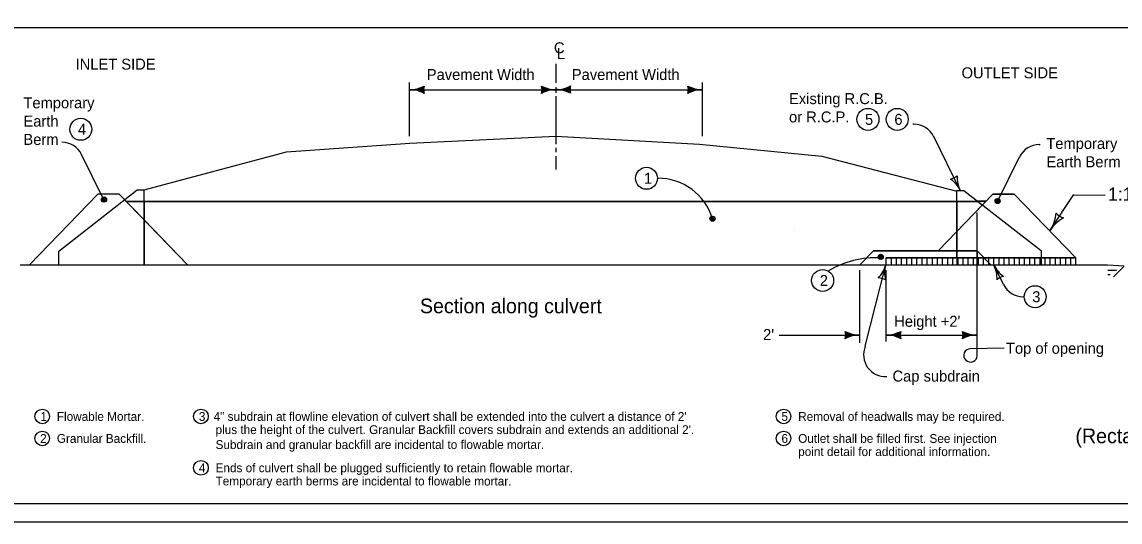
# Model space of a CAD drawing. Extents: x 4574 to 81668, y 5908 to 13780.
# Drawn here: x 10645 to 12144, y 7924 to 8607 of the extents above; entities that cross this region are included whole.
import ezdxf

# ---------------------------------------------------------------- set-up
doc = ezdxf.new("R2010")
doc.units = 0
for name, color, linetype in [('dsnCellElements', 7, 'Continuous'), ('DsnShtRevisedText', 7, 'Continuous'), ('Level 1', 7, 'Continuous'), ('Level 8', 7, 'Continuous'), ('SheetBorder', 7, 'Continuous'), ('ShtPlotIdentification', 7, 'Continuous')]:
    doc.layers.add(name, color=color, linetype=linetype)

msp = doc.modelspace()

# ---------------------------------------------------------------- linework, layer by layer
at = {"layer": 'dsnCellElements'}
for p, q in [((11373.8, 8523.5), (11373.8, 8549.6)), ((11173.8, 8450.5), (11173.8, 8524.1)), ((11373.8, 8509.9), (11373.8, 8517.4)), ((11573.8, 8450.5), (11573.8, 8524.1)), ((11173.8, 8514.1), (11193, 8514.1)), ((11173.8, 8514.1), (11373.8, 8514.1)), ((11373.9, 8514.1), (11354.7, 8514.1)), ((11373.7, 8514.2), (11392.9, 8514.2)), ((11373.8, 8514.1), (11573.8, 8514.1)), ((11373.8, 8439.9), (11373.8, 8505.4)), ((11573.8, 8514.1), (11554.6, 8514.1)), ((11862.4, 8467), (11861.1, 8467)), ((11005.8, 8429.1), (11174.4, 8440.9)), ((11174.4, 8440.9), (11373.7, 8450.6)), ((11373.7, 8450.6), (11569.9, 8439.8)), ((11925.6, 8376.4), (11889.4, 8450.3)), ((10756.6, 8363.6), (10726.1, 8425.8)), ((10811.4, 8377.2), (11005.8, 8429.1)), ((11373.8, 8429), (11373.8, 8434.7)), ((11569.9, 8439.8), (11736.7, 8423.2)), ((12033.6, 8439.3), (12034.9, 8439.3)), ((11373.8, 8405.3), (11373.8, 8423.2)), ((11736.7, 8423.2), (11920.8, 8375.7)), ((11976.1, 8360.4), (12006.6, 8422.6)), ((10654.8, 8275.1), (10748.1, 8371.7)), ((10694.9, 8293.9), (10801.9, 8377.2)), ((10777.2, 8371.7), (10748.1, 8371.7)), ((10870.7, 8274.9), (10777.2, 8371.7)), ((10801.9, 8377.2), (10811.4, 8377.2)), ((10811.4, 8361.7), (10811.4, 8377.2)), ((11895.6, 8294.3), (11970.3, 8371.7)), ((11920.8, 8376.4), (11930.5, 8376.4)), ((11920.8, 8361.7), (11920.8, 8376.4)), ((11930.5, 8376.3), (12036.5, 8294.1)), ((11970.3, 8371.7), (11999.4, 8371.7)), ((12083.6, 8284.5), (11999.4, 8371.7)), ((12048.4, 8322.2), (12080.6, 8371.2)), ((12080, 8370.3), (12123.6, 8370.4)), ((10786.9, 8361.7), (11949.3, 8361.7)), ((10811.4, 8361.7), (10811.3, 8275.1)), ((11920.8, 8361.7), (11920.8, 8275.1)), ((11949.2, 8361.8), (11960.7, 8361.8)), ((11948.7, 8151.4), (11948.7, 8346.4)), ((10695, 8274.9), (10695, 8293.9)), ((11788.7, 8275.1), (11807.3, 8294.3)), ((11807.3, 8294.3), (11948.7, 8294.3)), ((11967.3, 8275.1), (11948.7, 8294.3)), ((12036.4, 8275.1), (12036.4, 8294)), ((10642.2, 8275.1), (12126.8, 8275.1)), ((11788.7, 8168.6), (11788.7, 8267.9)), ((11796, 8163.9), (11823.9, 8275.1)), ((11824.5, 8170.2), (11824.5, 8267.9)), ((11984.7, 8248.3), (11971.6, 8274.9)), ((12126.8, 8275.1), (12149.3, 8273.7)), ((12139.2, 8267.4), (12127.2, 8267.4)), ((12130.5, 8261.6), (12127.2, 8261.6)), ((12130.5, 8261.6), (12130.5, 8261.6)), ((12148.8, 8272.9), (12134.7, 8258.8)), ((12136.3, 8267.4), (12136.3, 8267.4)), ((11678.6, 8179.2), (11788.5, 8179.2)), ((11788.5, 8179.2), (11769.3, 8179.2)), ((11824.5, 8179.2), (11843.7, 8179.2)), ((11824.5, 8179.2), (11948.7, 8179.2)), ((11948.7, 8179.2), (11929.5, 8179.2)), ((11985.8, 8161.1), (11939.6, 8160.5)), ((11801.2, 8132.6), (11802.1, 8131.6))]:
    msp.add_line(p, q, dxfattribs=at)
for points in [[(11192.6, 8510.6), (11191.9, 8514.1), (11192.6, 8517.7), (11188.3, 8515.7), (11181.5, 8514.1), (11188.8, 8512.4), (11192, 8511), (11191.2, 8514.1), (11191.5, 8516.4), (11188.7, 8515.1), (11184.9, 8514.1), (11188.9, 8513), (11191, 8512.2), (11190.6, 8515.3), (11187.9, 8514.1), (11190, 8513.4), (11190.1, 8514.5), (11189.1, 8514.2)], [(11355.1, 8517.7), (11355.8, 8514.1), (11355.1, 8510.5), (11359.4, 8512.6), (11366.2, 8514.1), (11358.9, 8515.8), (11355.7, 8517.3), (11356.5, 8514.1), (11356.2, 8511.8), (11359, 8513.2), (11362.8, 8514.1), (11358.8, 8515.3), (11356.7, 8516), (11357.1, 8513), (11359.9, 8514.1), (11357.7, 8514.8), (11357.6, 8513.8), (11358.7, 8514.1)], [(11392.5, 8510.6), (11391.8, 8514.2), (11392.6, 8517.8), (11388.3, 8515.7), (11381.5, 8514.2), (11388.8, 8512.5), (11391.9, 8511.1), (11391.2, 8514.2), (11391.5, 8516.5), (11388.6, 8515.2), (11384.9, 8514.2), (11388.9, 8513), (11391, 8512.3), (11390.6, 8515.4), (11387.8, 8514.2), (11390, 8513.5), (11390, 8514.6), (11389, 8514.2)], [(11554.9, 8517.7), (11555.7, 8514.1), (11554.9, 8510.5), (11559.2, 8512.6), (11566, 8514.1), (11558.7, 8515.8), (11555.5, 8517.2), (11556.3, 8514.1), (11556, 8511.8), (11558.9, 8513.1), (11562.6, 8514.1), (11558.6, 8515.3), (11556.5, 8516), (11556.9, 8512.9), (11559.7, 8514.1), (11557.5, 8514.8), (11557.5, 8513.7), (11558.5, 8514.1)], [(10757, 8367.3), (10755.8, 8366.8), (10754, 8366.2), (10753.6, 8364.4), (10753.9, 8362.7), (10755.1, 8361.2), (10756.8, 8361.4), (10758.7, 8361.6), (10759.5, 8363.1), (10759.7, 8364.7), (10758.6, 8366.7), (10757.3, 8366.8), (10755.4, 8366.4), (10753.9, 8365.2), (10754, 8363.5), (10755.1, 8362.1), (10756.8, 8361.9), (10758.6, 8362.3), (10758.9, 8363.3), (10759.3, 8364.5), (10758.4, 8366.1), (10757.1, 8366), (10755.6, 8365.8), (10754.4, 8364.9), (10755, 8363.4), (10756.2, 8362.5), (10757.7, 8362.4), (10758.1, 8363.3), (10758.6, 8364.2), (10757.8, 8365.4), (10756.7, 8365.7), (10755.7, 8365.2), (10755.6, 8364), (10756.1, 8363.2), (10757.2, 8362.9), (10757.7, 8363.4), (10758, 8364), (10757.4, 8364.9), (10756.7, 8365.1), (10756, 8364.6), (10756.1, 8364), (10756.6, 8363.6), (10757.4, 8363.7), (10757.3, 8364.2), (10756.7, 8364.5)], [(11977, 8365.3), (11975.8, 8364.8), (11974, 8364.2), (11973.6, 8362.3), (11973.8, 8360.7), (11975, 8359.2), (11976.8, 8359.3), (11978.6, 8359.6), (11979.5, 8361.1), (11979.7, 8362.6), (11978.6, 8364.6), (11977.2, 8364.8), (11975.4, 8364.3), (11973.9, 8363.2), (11973.9, 8361.4), (11975.1, 8360), (11976.8, 8359.8), (11978.6, 8360.2), (11978.9, 8361.2), (11979.3, 8362.5), (11978.4, 8364), (11977, 8364), (11975.5, 8363.7), (11974.4, 8362.9), (11975, 8361.3), (11976.1, 8360.4), (11977.7, 8360.4), (11978.1, 8361.2), (11978.5, 8362.2), (11977.8, 8363.4), (11976.6, 8363.6), (11975.6, 8363.1), (11975.6, 8362), (11976.1, 8361.2), (11977.1, 8360.9), (11977.6, 8361.3), (11977.9, 8361.9), (11977.4, 8362.8), (11976.7, 8363), (11976, 8362.6), (11976.1, 8362), (11976.6, 8361.6), (11977.3, 8361.6), (11977.3, 8362.1), (11976.7, 8362.4)], [(11587.7, 8341.2), (11586.5, 8340.7), (11584.6, 8340.1), (11584.3, 8338.2), (11584.5, 8336.6), (11585.7, 8335.1), (11587.5, 8335.2), (11589.3, 8335.5), (11590.2, 8337), (11590.4, 8338.5), (11589.3, 8340.5), (11587.9, 8340.7), (11586.1, 8340.2), (11584.6, 8339.1), (11584.6, 8337.3), (11585.8, 8335.9), (11587.4, 8335.7), (11589.3, 8336.1), (11589.6, 8337.1), (11589.9, 8338.4), (11589.1, 8339.9), (11587.7, 8339.9), (11586.2, 8339.6), (11585.1, 8338.8), (11585.7, 8337.2), (11586.8, 8336.3), (11588.4, 8336.3), (11588.7, 8337.1), (11589.2, 8338.1), (11588.5, 8339.3), (11587.3, 8339.5), (11586.3, 8339), (11586.3, 8337.9), (11586.8, 8337.1), (11587.8, 8336.8), (11588.3, 8337.2), (11588.6, 8337.8), (11588.1, 8338.7), (11587.4, 8338.9), (11586.6, 8338.5), (11586.8, 8337.9), (11587.3, 8337.5), (11588, 8337.5), (11588, 8338), (11587.4, 8338.3)], [(11817.4, 8289.1), (11816.2, 8288.5), (11814.3, 8288), (11814, 8286.1), (11814.2, 8284.5), (11815.4, 8283), (11817.2, 8283.1), (11819, 8283.4), (11819.9, 8284.8), (11820.1, 8286.4), (11819, 8288.4), (11817.6, 8288.6), (11815.8, 8288.1), (11814.3, 8286.9), (11814.3, 8285.2), (11815.5, 8283.8), (11817.2, 8283.6), (11819, 8284), (11819.3, 8285), (11819.6, 8286.3), (11818.8, 8287.8), (11817.4, 8287.8), (11815.9, 8287.5), (11814.8, 8286.7), (11815.4, 8285.1), (11816.5, 8284.2), (11818.1, 8284.2), (11818.4, 8285), (11818.9, 8285.9), (11818.2, 8287.2), (11817, 8287.4), (11816, 8286.9), (11816, 8285.8), (11816.5, 8285), (11817.5, 8284.7), (11818, 8285.1), (11818.3, 8285.7), (11817.8, 8286.6), (11817.1, 8286.8), (11816.4, 8286.4), (11816.5, 8285.8), (11817, 8285.4), (11817.7, 8285.4), (11817.7, 8285.9), (11817.1, 8286.2)], [(11769.7, 8182.7), (11770.4, 8179.2), (11769.6, 8175.6), (11773.9, 8177.6), (11780.8, 8179.2), (11773.4, 8180.9), (11770.3, 8182.3), (11771.1, 8179.2), (11770.8, 8176.8), (11773.6, 8178.2), (11777.4, 8179.2), (11773.3, 8180.3), (11771.2, 8181.1), (11771.6, 8178), (11774.4, 8179.2), (11772.2, 8179.9), (11772.2, 8178.8), (11773.2, 8179.1)], [(11843.3, 8175.7), (11842.6, 8179.3), (11843.3, 8182.9), (11839, 8180.8), (11832.2, 8179.3), (11839.6, 8177.5), (11842.7, 8176.1), (11841.9, 8179.3), (11842.2, 8181.6), (11839.4, 8180.2), (11835.6, 8179.3), (11839.7, 8178.1), (11841.8, 8177.4), (11841.4, 8180.4), (11838.6, 8179.3), (11840.8, 8178.6), (11840.8, 8179.6), (11839.8, 8179.3)], [(11929.9, 8182.7), (11930.6, 8179.2), (11929.9, 8175.6), (11934.2, 8177.6), (11941, 8179.2), (11933.6, 8180.9), (11930.5, 8182.3), (11931.3, 8179.2), (11931, 8176.8), (11933.8, 8178.2), (11937.6, 8179.2), (11933.6, 8180.3), (11931.5, 8181.1), (11931.8, 8178), (11934.6, 8179.2), (11932.4, 8179.9), (11932.4, 8178.8), (11933.4, 8179.1)]]:
    msp.add_lwpolyline(points, dxfattribs=at)
for centre, radius in [((11799.6, 8473.6), 15), ((11839.6, 8473.6), 15), ((10725, 8460.1), 15), ((11497.3, 8393.2), 15), ((10756.7, 8364.1), 3.5), ((11976.7, 8362.1), 3.5), ((11587.4, 8338), 3.5), ((11817.1, 8285.9), 3.5), ((11737.8, 8253.7), 15), ((12027.9, 8231.5), 15), ((10672.3, 8068.1), 10), ((10889, 8068.1), 10), ((11684.4, 8068.1), 10), ((10672.3, 8038.1), 10), ((11684.4, 8038.1), 10), ((10889, 7998), 10)]:
    msp.add_circle(centre, radius, dxfattribs=at)
for centre, radius, start, end in [((11173.8, 8556.6), 42.5, 270, 298.0725), ((11209.4, 8514.1), 16.4, 162.2666, 197.7334), ((11338.3, 8514.1), 16.4, 342.2666, 17.7334), ((11373.9, 8556.6), 42.5, 241.9275, 270), ((11373.7, 8556.7), 42.5, 270, 298.0725), ((11409.4, 8514.2), 16.4, 162.2666, 197.7334), ((11538.1, 8514.1), 16.4, 342.2666, 17.7334), ((11573.8, 8556.6), 42.5, 241.9275, 270), ((11173.8, 8471.6), 42.5, 61.9275, 90), ((11373.9, 8471.6), 42.5, 90, 118.0725), ((11373.7, 8471.7), 42.5, 61.9275, 90), ((11573.8, 8471.6), 42.5, 90, 118.0725), ((11862.4, 8437), 30, 26.1599, 90), ((10699.2, 8412.5), 30, 26.1603, 90), ((12033.6, 8409.3), 30, 90, 153.8397), ((11909.9, 8408.4), 16.4, 278.427, 313.8937), ((11963.8, 8395.2), 42.5, 178.0879, 206.1604), ((11513.3, 8316), 77.2, 16.5237, 90.8016), ((11887.5, 8357.7), 42.5, 26.1604, 54.2328), ((12005.6, 8350.4), 51.2, 326.6555, 354.7279), ((12091.2, 8294.1), 51.2, 118.583, 146.6555), ((12072, 8358.1), 19.8, 218.9221, 254.3888), ((11811.2, 8156), 128.8, 87.6655, 120.5189), ((11782.8, 8286.1), 42.5, 316.8529, 344.9253), ((11864.9, 8264), 42.5, 164.9253, 192.9978), ((11933.4, 8256.2), 42.5, 358.0872, 26.1597), ((12009.7, 8293.7), 42.5, 206.1597, 234.2322), ((11814.6, 8240.7), 16.4, 57.192, 92.6587), ((11987.3, 8243), 16.4, 98.4264, 133.8931), ((12011.6, 8261.5), 30, 206.1604, 270), ((11752.9, 8179.2), 16.4, 342.2666, 17.7334), ((11788.5, 8221.7), 42.5, 241.9275, 270), ((11788.5, 8136.7), 42.5, 90, 118.0725), ((11824.5, 8221.7), 42.5, 270, 298.0725), ((11824.5, 8136.7), 42.5, 61.9275, 90), ((11860.1, 8179.2), 16.4, 162.2666, 197.7334), ((11913.1, 8179.2), 16.4, 342.2666, 17.7334), ((11948.7, 8221.7), 42.5, 241.9275, 270), ((11948.7, 8136.7), 42.5, 90, 118.0725), ((11823.7, 8152.4), 30, 157.6234, 272.9348)]:
    msp.add_arc(centre, radius, start, end, dxfattribs=at)
at = {"layer": 'Level 1'}
for points in [[(10147.5, 8599), (13252.5, 8599), (13252.5, 7949), (10147.5, 7949), (10147.5, 8599)], [(10811.4, 8361.7), (10786.9, 8361.7), (10811.4, 8336.4), (10811.4, 8361.7)]]:
    msp.add_lwpolyline(points, dxfattribs=at)
for points in [[(10777.2, 8371.7), (10748.1, 8371.7), (10654.8, 8275.1), (10811.3, 8275.1), (10811.4, 8336.4)], [(10777.2, 8371.7), (10748.1, 8371.7), (10654.8, 8275.1), (10811.3, 8275.1), (10811.4, 8336.4)], [(12083.6, 8284.5), (12083.6, 8284.5), (11999.4, 8371.7), (11970.3, 8371.7), (11920.8, 8320.4), (11920.8, 8294.3), (11948.7, 8294.3), (11958.2, 8284.5)], [(11920.8, 8320.4), (11920.8, 8361.7), (10811.4, 8361.7), (10811.4, 8336.4), (10870.5, 8275.1), (11788.7, 8275.1), (11807.3, 8294.3), (11895.6, 8294.3)], [(11955.8, 8356.7), (11949.3, 8361.7), (11920.8, 8361.7), (11920.8, 8320.4)], [(11960.7, 8361.8), (11949.2, 8361.8), (11955.8, 8356.7)], [(10811.3, 8275.1), (10870.5, 8275.1), (10811.4, 8336.4)], [(11920.8, 8294.3), (11920.8, 8320.4), (11895.6, 8294.3)], [(11920.8, 8294.3), (11807.3, 8294.3), (11788.7, 8275.1), (11824.6, 8275.1), (11824.6, 8284.5), (11920.8, 8284.5)], [(11948.7, 8284.5), (11948.7, 8294.3), (11920.8, 8294.3), (11920.8, 8284.5)], [(11958.2, 8284.5), (11948.7, 8294.3), (11948.7, 8284.5)]]:
    msp.add_lwpolyline(points, close=True, dxfattribs=at)
for centre in [(10756.7, 8364.1), (10756.7, 8364.1), (11976.7, 8362.1), (11587.4, 8338)]:
    msp.add_circle(centre, 3.5, dxfattribs=at)
at = {"layer": 'Level 8'}
for p, q in [((11824.6, 8274.9), (11824.6, 8284.5)), ((12083.6, 8284.5), (11824.6, 8284.5)), ((11831.6, 8274.9), (11831.6, 8284.5)), ((11838.6, 8274.9), (11838.6, 8284.5)), ((11845.6, 8274.9), (11845.6, 8284.5)), ((11852.6, 8274.9), (11852.6, 8284.5)), ((11859.6, 8274.9), (11859.6, 8284.5)), ((11866.6, 8274.9), (11866.6, 8284.5)), ((11873.6, 8274.9), (11873.6, 8284.5)), ((11880.6, 8274.9), (11880.6, 8284.5)), ((11887.6, 8274.9), (11887.6, 8284.5)), ((11894.6, 8274.9), (11894.6, 8284.5)), ((11901.6, 8274.9), (11901.6, 8284.5)), ((11908.6, 8274.9), (11908.6, 8284.5)), ((11915.6, 8274.9), (11915.6, 8284.5)), ((11922.6, 8274.9), (11922.6, 8284.5)), ((11929.6, 8274.9), (11929.6, 8284.5)), ((11936.6, 8274.9), (11936.6, 8284.5)), ((11943.6, 8274.9), (11943.6, 8284.5)), ((11950.6, 8274.9), (11950.6, 8284.5)), ((11957.6, 8274.9), (11957.6, 8284.5)), ((11964.6, 8274.9), (11964.6, 8284.5)), ((11971.6, 8274.9), (11971.6, 8284.5)), ((11978.6, 8274.9), (11978.6, 8284.5)), ((11985.6, 8274.9), (11985.6, 8284.5)), ((11992.6, 8274.9), (11992.6, 8284.5)), ((11999.6, 8274.9), (11999.6, 8284.5)), ((12006.6, 8274.9), (12006.6, 8284.5)), ((12013.6, 8274.9), (12013.6, 8284.5)), ((12020.6, 8274.9), (12020.6, 8284.5)), ((12027.6, 8274.9), (12027.6, 8284.5)), ((12034.6, 8274.9), (12034.6, 8284.5)), ((12041.6, 8274.9), (12041.6, 8284.5)), ((12048.6, 8274.9), (12048.6, 8284.5)), ((12055.6, 8274.9), (12055.6, 8284.5)), ((12062.6, 8274.9), (12062.6, 8284.5)), ((12069.6, 8274.9), (12069.6, 8284.5)), ((12076.6, 8274.9), (12076.6, 8284.5)), ((12083.6, 8274.9), (12083.6, 8284.5))]:
    msp.add_line(p, q, dxfattribs=at)
at = {"layer": 'SheetBorder'}
msp.add_lwpolyline([(10132.5, 9944), (13267.5, 9944), (13267.5, 7924), (10132.5, 7924)], close=True, dxfattribs=at)
at = {"layer": 'ShtPlotIdentification'}
msp.add_line((11700, 8321.5), (11700, 8321.5), dxfattribs=at)
msp.add_arc((11939.6, 8151.4), 9.1, 90, 0.0003, dxfattribs=at)

# ---------------------------------------------------------------- texts
at = {"layer": 'dsnCellElements'}
msp.add_text('1:1 Typ.', height=18.09, dxfattribs=at).set_placement((12127.4, 8362.6))
at = {"layer": 'DsnShtRevisedText'}
for s, height, p in [('C', 15, (11371, 8563.8)), ('L', 15, (11375, 8555.9)), ('1', 15, (11493.9, 8385.7)), ('2', 15, (11733.9, 8246.2)), ('3', 15, (12024, 8224)), ('Cap subdrain', 15, (11833.2, 8115.7)), ('4" subdrain at flowline elevation of culvert shall be extended into the culvert a distance of 2\'  ', 12, (10906.4, 8062.1)), ("plus the height of the culvert. Granular Backfill covers subdrain and extends an additional 2'.", 12, (10909, 8044.1)), ("(Rectangular structures less than 8' in either height or width. ", 20, (12082.9, 8031.6)), ('Subdrain and granular backfill are incidental to flowable mortar.', 12, (10909, 8023.7))]:
    msp.add_text(s, height=height, dxfattribs=at).set_placement(p)
for s, height, rotation, p in [('INLET SIDE', 15, 0.0185, (10717.9, 8541.4)), ('Pavement Width', 15, 359.9814, (11197.4, 8527.3)), ('Pavement Width', 15, 359.9814, (11395.4, 8527.3)), ('OUTLET SIDE', 15, 0.0185, (11927.5, 8529.6)), ('Temporary ', 15, 0.0185, (10646.7, 8488.7)), ('Existing R.C.B. ', 15, 359.9819, (11691.9, 8494.4)), ('Earth ', 15, 0.0185, (10646.7, 8463.7)), ('or R.C.P.', 15, 359.9819, (11691.9, 8469.4)), ('5', 15, 359.9815, (11795.6, 8466.1)), ('6', 15, 359.9815, (11835.7, 8466.1)), ('4', 15, 0.0185, (10721.1, 8452.6)), ('Berm', 15, 0.0185, (10646.7, 8438.7)), ('Temporary ', 15, 359.9815, (12043.2, 8433.2)), ('Earth Berm', 15, 359.9815, (12043.2, 8408.2)), ('Section along culvert', 20, 359.9815, (11188, 8209)), ("Height +2'", 15, 359.9814, (11835.5, 8190.5)), ("2'", 15, 359.9814, (11656.5, 8172.4)), ('Top of opening', 15, 0.0185, (11988.1, 8153.6)), ('1', 12, 359.9815, (10669.9, 8062.1)), ('Flowable Mortar.', 12, 359.9817, (10692.3, 8062.1)), ('3', 12, 359.9791, (10886.2, 8062.1)), ('5', 12, 359.9815, (11681.5, 8062.1)), ('Removal of headwalls may be required.', 12, 359.9815, (11704.4, 8062.1)), ('2', 12, 359.9817, (10669.5, 8032.1)), ('Granular Backfill.', 12, 359.9806, (10692.3, 8032.1)), ('6', 12, 359.9815, (11681.6, 8032.1)), ('Outlet shall be filled first. See injection ', 12, 359.9815, (11704.4, 8032.1)), ('point detail for additional information.', 12, 359.9815, (11704.4, 8014.1)), ('4', 12, 359.9815, (10886.2, 7992)), ('Ends of culvert shall be plugged sufficiently to retain flowable mortar.', 12, 359.9815, (10909, 7992)), ('Temporary earth berms are incidental to flowable mortar.', 12, 359.9815, (10909, 7974))]:
    msp.add_text(s, height=height, rotation=rotation, dxfattribs=at).set_placement(p)

doc.saveas('drawing.dxf')
